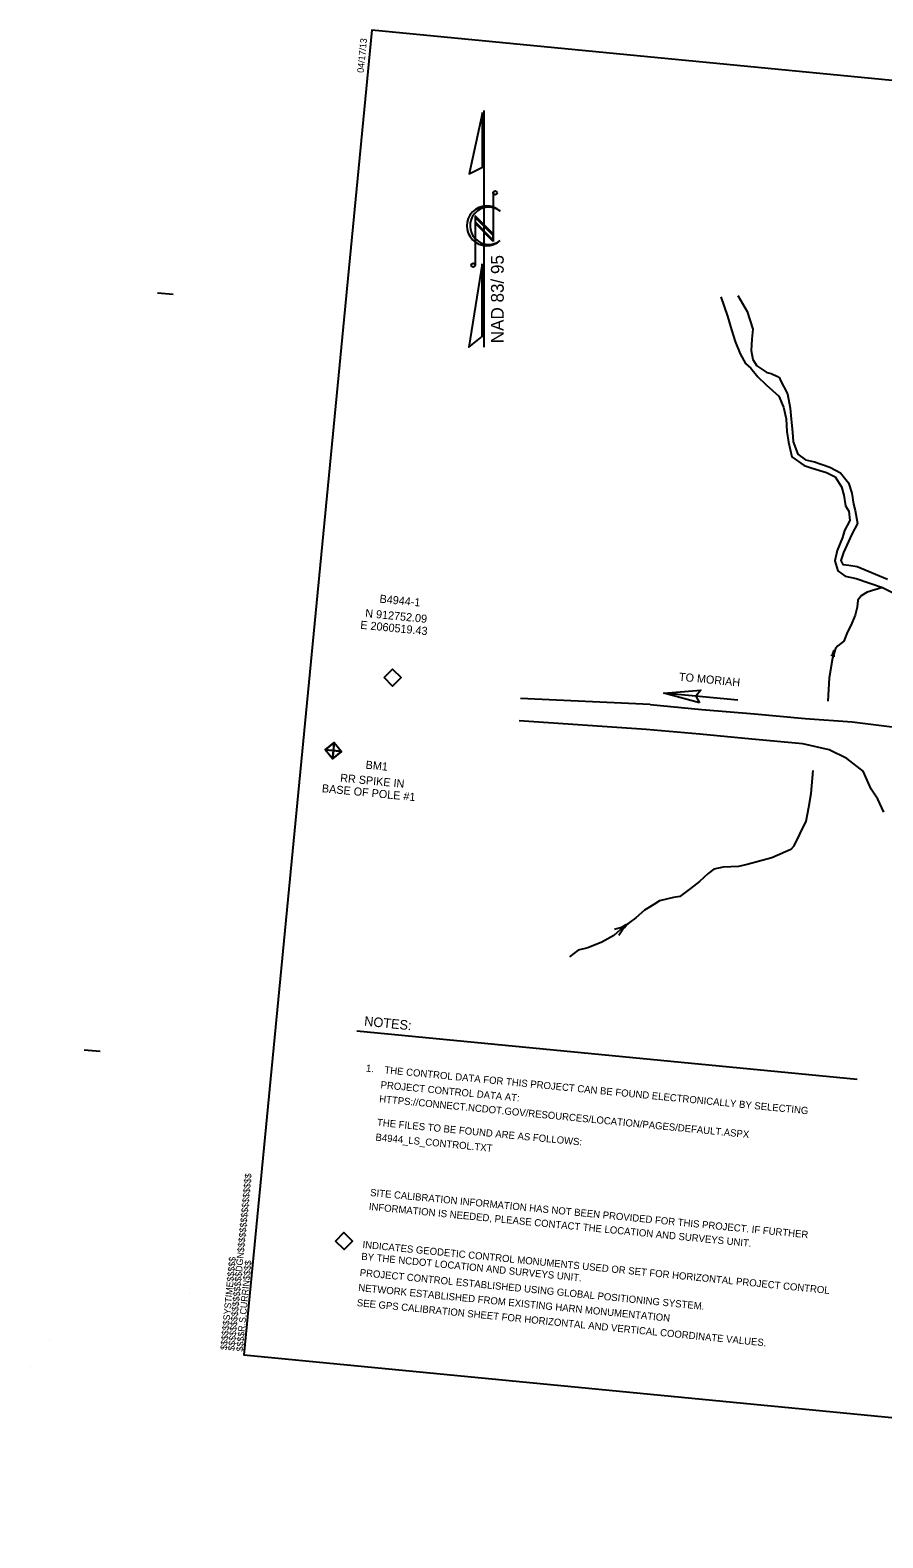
# Model space of a CAD drawing. Extents: x 2060504 to 2061945, y 912229 to 913160.
# Drawn here: x 2060504 to 2061030, y 912229 to 913160 of the extents above; entities that cross this region are included whole.
import ezdxf

# ---------------------------------------------------------------- set-up
doc = ezdxf.new("R2010")
doc.units = 0
for name, color, linetype in [('CTL Bench Mark CELL', 7, 'Continuous'), ('CTL Bench Mark Text', 7, 'Continuous'), ('CTL Sheet Border CELL', 7, 'Continuous'), ('CTL Sheet Notes CELL', 7, 'Continuous'), ('CTL Supplemental Horizontal and Vertical CELL', 7, 'Continuous'), ('Exist Hydro Jurisdictional Stream or Body of Water', 7, 'Continuous'), ('Exist Hydro Stream Flow Arrow CELL', 7, 'Continuous'), ('Exist Hydro Stream or Body of Water', 7, 'Continuous'), ('Exist Roads Soil', 7, 'Continuous'), ('Prop Terminator CELL', 7, 'Continuous'), ('Sheet Data Field CELL', 7, 'Continuous'), ('Sheet North Arrow CELL', 7, 'Continuous')]:
    doc.layers.add(name, color=color, linetype=linetype)

# ---------------------------------------------------------------- blocks, each defined once
blk = doc.blocks.new('EXIST HYDRO STREAM FLOW ARROW')
at = {"layer": 'Exist Hydro Stream Flow Arrow CELL'}
blk.add_line((0, 0), (0, 0), dxfattribs=at)
for points in [[(-0.1, 0.04575), (-0.07325, 0.03375), (-0.04475, 0.0245), (-0.0165, 0.01575), (0.01175, 0.0095), (0.041, 0.00475), (0.07075, 0.0015), (0.1, 0)], [(-0.1, -0.04575), (-0.07325, -0.03375), (-0.04475, -0.0245), (-0.0165, -0.01575), (0.01175, -0.0095), (0.041, -0.00475), (0.07075, -0.0015), (0.1, 0)]]:
    blk.add_lwpolyline(points, dxfattribs=at)

msp = doc.modelspace()

# ---------------------------------------------------------------- linework, layer by layer
at = {"layer": 'CTL Bench Mark CELL'}
msp.add_line((2060690.76, 912715.17), (2060690.76, 912715.17), dxfattribs=at)
msp.add_lwpolyline([(2060685.7, 912715.65), (2060691.26, 912720.22), (2060695.82, 912714.66), (2060690.27, 912710.1)], close=True, dxfattribs=at)
for points in [[(2060691.26, 912720.22), (2060690.27, 912710.1), (2060690.76, 912715.16), (2060695.82, 912714.66), (2060685.7, 912715.65)], [(2060690.76, 912715.16), (2060691.26, 912720.22), (2060685.7, 912715.65), (2060690.76, 912715.16)], [(2060690.76, 912715.16), (2060690.27, 912710.1), (2060695.82, 912714.66), (2060690.76, 912715.16)]]:
    msp.add_lwpolyline(points, dxfattribs=at)
at = {"layer": 'CTL Sheet Border CELL'}
for p, q in [((2060582.11, 912997.84), (2060591.84, 912996.9)), ((2060536.93, 912530.45), (2060546.66, 912529.51)), ((2060602.11, 912380.06), (2060602.11, 912380.06)), ((2060602.11, 912380.06), (2060602.11, 912380.06)), ((2060515.32, 912351.66), (2060515.32, 912351.66)), ((2060635.47, 912342.05), (2060635.47, 912342.05)), ((2060635.47, 912342.05), (2060635.47, 912342.05)), ((2060635.47, 912342.05), (2060635.47, 912342.05)), ((2060635.47, 912342.05), (2060635.47, 912342.05)), ((2060635.47, 912342.05), (2060635.47, 912342.05)), ((2060635.47, 912342.05), (2060635.47, 912342.05)), ((2060635.47, 912342.05), (2060635.47, 912342.05)), ((2060635.47, 912342.05), (2060635.47, 912342.05)), ((2060635.47, 912342.05), (2060635.47, 912342.05)), ((2060635.47, 912342.05), (2060635.47, 912342.05)), ((2060635.47, 912342.05), (2060635.47, 912342.05)), ((2060503.5, 912335.15), (2060503.5, 912335.15))]:
    msp.add_line(p, q, dxfattribs=at)
msp.add_lwpolyline([(2061883, 913047.03), (2060714.54, 913159.97), (2060635.47, 912342.05), (2061803.94, 912229.1)], close=True, dxfattribs=at)
for points in [[(2060631.32, 912377.23), (2060631.32, 912377.23)], [(2060631.32, 912377.23), (2060631.32, 912377.23)], [(2060664.69, 912339.23), (2060664.69, 912339.23)], [(2060664.69, 912339.23), (2060664.69, 912339.23)]]:
    msp.add_lwpolyline(points, dxfattribs=at)
at = {"layer": 'CTL Sheet Notes CELL'}
msp.add_line((2060705.3, 912542.22), (2061014.18, 912512.36), dxfattribs=at)
at = {"layer": 'CTL Supplemental Horizontal and Vertical CELL'}
for p, q in [((2060727.32, 912760.25), (2060727.32, 912760.25)), ((2060697.31, 912412.34), (2060697.31, 912412.34))]:
    msp.add_line(p, q, dxfattribs=at)
for points in [[(2060722.11, 912760.26), (2060727.35, 912765.51), (2060732.6, 912760.26), (2060727.36, 912755.01)], [(2060692.09, 912412.35), (2060697.34, 912417.59), (2060702.59, 912412.34), (2060697.35, 912407.1)]]:
    msp.add_lwpolyline(points, close=True, dxfattribs=at)
at = {"layer": 'Exist Hydro Jurisdictional Stream or Body of Water'}
for points in [[(2060929.98, 912995.34), (2060934.16, 912983.33), (2060936.63, 912974.98), (2060939.02, 912967.69), (2060942.1, 912960.23), (2060945.31, 912954.23), (2060948.55, 912951.35), (2060952.86, 912945.93), (2060958.18, 912940.97), (2060965.85, 912933.99), (2060968.7, 912927.22), (2060970.5, 912919.92), (2060970.92, 912912.26), (2060971.81, 912905.61), (2060973.92, 912896.46), (2060981.47, 912891.19), (2060986.43, 912889.46), (2060995.43, 912886.83), (2061000.78, 912884.21), (2061004.52, 912878.09), (2061006.09, 912872.96), (2061007.12, 912866.3), (2061009.14, 912862.9), (2061009.67, 912857.29), (2061006.56, 912851.08), (2061005.14, 912846.72), (2061001.9, 912838.78), (2061000.45, 912832.28), (2061002.25, 912826.14), (2061006.97, 912822.78), (2061013.64, 912821.5), (2061029.97, 912815.9), (2061040.31, 912810.63)], [(2060940.53, 912996.22), (2060946.26, 912986.22), (2060949.78, 912975.29), (2060949.15, 912969.19), (2060948.85, 912962.29), (2060949.93, 912956.68), (2060952.26, 912952.75), (2060958.51, 912948.61), (2060961.18, 912947.94), (2060965.13, 912946.17), (2060966.32, 912945.33), (2060966.91, 912943.59), (2060971.27, 912935.35), (2060972.99, 912926.62), (2060973.43, 912919.77), (2060974.35, 912911.81), (2060974.73, 912905.72), (2060977.66, 912898.19), (2060982.47, 912894.78), (2060987.9, 912893.36), (2060997.5, 912890.13), (2061004.09, 912886.61), (2061008.97, 912880.43), (2061010.92, 912874.07), (2061011.96, 912867.37), (2061013.14, 912863.3), (2061014.56, 912855.33), (2061010.99, 912848.88), (2061008.99, 912844.33), (2061005.74, 912837.45), (2061004.24, 912832.54), (2061005.45, 912830.03), (2061009.05, 912829.56), (2061014.35, 912828.84), (2061033.04, 912820.93)]]:
    msp.add_lwpolyline(points, dxfattribs=at)
at = {"layer": 'Exist Hydro Stream or Body of Water'}
for points in [[(2061029.97, 912815.9), (2061020.38, 912812.95), (2061016.81, 912810.63), (2061014.66, 912808.08), (2061014.37, 912803.65), (2061013.1, 912798.86), (2061010.89, 912793.76), (2061007.9, 912787.55), (2061006.04, 912782.74), (2061002.42, 912779.79), (2061000.81, 912778.16), (2060999.05, 912772.31), (2060997.07, 912760.16), (2060996.22, 912745.59)], [(2060973.25, 912654.18), (2060975.4, 912656.3), (2060978.82, 912663.48), (2060982.77, 912671.49), (2060984.48, 912680.26), (2060985.77, 912688.73), (2060987.17, 912702.89)], [(2060973.25, 912654.18), (2060961.52, 912649), (2060946.34, 912644.77), (2060940.96, 912643.7), (2060931.5, 912643.28), (2060925.67, 912642.01), (2060922.27, 912639.32), (2060916.97, 912634.43), (2060911.4, 912630.07), (2060904.68, 912625.12), (2060900.78, 912624.42), (2060892.16, 912622.37), (2060888.71, 912620.12), (2060882.89, 912616.64), (2060877.51, 912611.95), (2060869.79, 912606.07), (2060864.04, 912600.9), (2060856.53, 912596.9), (2060848.02, 912593.44), (2060841.95, 912591.92), (2060836.52, 912587.91)]]:
    msp.add_lwpolyline(points, dxfattribs=at)
at = {"layer": 'Exist Roads Soil'}
for points in [[(2060886.37, 912743.53), (2060806.37, 912747.43)], [(2060886.37, 912743.53), (2060918.27, 912740.51), (2060950.89, 912737.85), (2060982.11, 912734.98), (2061011.2, 912732.95), (2061042.39, 912729.02), (2061075.76, 912726.94), (2061092.95, 912725.5)], [(2060883.98, 912728.25), (2060805.57, 912733.45)], [(2061023.03, 912691.3), (2061017.95, 912702.36), (2061007.88, 912710.22), (2060996.93, 912715.54), (2060980.63, 912719.42), (2060949.3, 912722.16), (2060917.11, 912725.29), (2060883.98, 912728.25)], [(2061030.78, 912677.17), (2061026.96, 912685.13), (2061023.03, 912691.3)]]:
    msp.add_lwpolyline(points, dxfattribs=at)
at = {"layer": 'Prop Terminator CELL'}
msp.add_lwpolyline([(2060916.93, 912744.7), (2060894.91, 912750.72), (2060917.81, 912752.52), (2060914.56, 912748.82)], close=True, dxfattribs=at)
at = {"layer": 'Sheet Data Field CELL'}
msp.add_line((2060940.66, 912746.3), (2060894.91, 912750.72), dxfattribs=at)
at = {"layer": 'Sheet North Arrow CELL'}
for p, q in [((2060783.96, 912964.22), (2060783.96, 913110.47)), ((2060789.47, 913059.57), (2060789.47, 913029.56)), ((2060789.47, 913034.24), (2060778.29, 913045.42)), ((2060778.29, 913045.42), (2060778.29, 913014.91)), ((2060789.47, 913033.13), (2060778.29, 913044.32)), ((2060778.29, 913044.32), (2060778.29, 913041.57)), ((2060793.61, 913048.39), (2060793.77, 913048.28)), ((2060789.47, 913030.39), (2060778.29, 913041.57)), ((2060778.29, 913041.57), (2060789.47, 913030.39)), ((2060789.47, 913029.56), (2060778.29, 913040.74)), ((2060789.47, 913030.39), (2060789.47, 913033.13))]:
    msp.add_line(p, q, dxfattribs=at)
for points in [[(2060782.94, 913109.18), (2060774.6, 913071.2), (2060782.94, 913075.43)], [(2060782.76, 913015.74), (2060774.48, 912964.22), (2060782.76, 912970.74)]]:
    msp.add_lwpolyline(points, close=True, dxfattribs=at)
for centre in [(2060790.66, 913059.55), (2060777.1, 913014.86)]:
    msp.add_circle(centre, 1.19, dxfattribs=at)
for centre, radius, start, end in [((2060785.51, 913039.17), 12.29, 47.84002, 312.39406), ((2060786.7, 913039.17), 11.52, 53.09504, 308.62871)]:
    msp.add_arc(centre, radius, start, end, dxfattribs=at)

# ---------------------------------------------------------------- block references
at = {"layer": 'Exist Hydro Stream Flow Arrow CELL'}
for p, xscale, yscale, rotation in [((2060999.67, 912775.19), 20, 20.000000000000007, 77.64096278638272), ((2060869.79, 912606.07), 50, 50, 36.87182818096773)]:
    msp.add_blockref('EXIST HYDRO STREAM FLOW ARROW', p, dxfattribs=dict(at, xscale=xscale, yscale=yscale, rotation=rotation))

# ---------------------------------------------------------------- texts
at = {"layer": 'CTL Bench Mark Text'}
for s, p in [('N 912752.09', (2060710.27, 912797.65)), ('B4944-1', (2060719.12, 912806.53)), ('E 2060519.43', (2060707.24, 912790.41)), ('RR SPIKE IN ', (2060694.81, 912695.96)), ('BM1', (2060710.53, 912704)), ('BASE OF POLE #1', (2060683.51, 912689.52))]:
    msp.add_text(s, height=5, rotation=354.47872, dxfattribs=at).set_placement(p)
at = {"layer": 'CTL Sheet Border CELL'}
for s, height, p in [('04/17/13', 4.109, (2060709.51, 913133.48)), ('$$$$$$$$$$$$$$$$DGN$$$$$$$$$$$$$$$$', 4.1087, (2060629.7, 912344.46)), ('$$$$$$SYSTIME$$$$$', 4.1087, (2060624.99, 912344.92)), ('$$$$R.S.CURRIN$$$$', 4.1087, (2060634.82, 912343.98))]:
    msp.add_text(s, height=height, rotation=84.4787, dxfattribs=at).set_placement(p)
at = {"layer": 'CTL Sheet Notes CELL'}
for s, height, rotation, p in [('NOTES:', 5.884, 354.37345, (2060709.63, 912545.33)), ('1.    THE CONTROL DATA FOR THIS PROJECT CAN BE FOUND ELECTRONICALLY BY SELECTING', 4.4127, 354.4787, (2060710.74, 912517.01)), ('PROJECT CONTROL DATA AT:', 4.4127, 354.4787, (2060719.79, 912506.75)), ('HTTPS://CONNECT.NCDOT.GOV/RESOURCES/LOCATION/PAGES/DEFAULT.ASPX', 4.4127, 354.4787, (2060718.95, 912498.04)), ('THE FILES TO BE FOUND ARE AS FOLLOWS:', 4.4127, 354.4787, (2060717.55, 912483.53)), ('B4944_LS_CONTROL.TXT', 4.4127, 354.4787, (2060716.67, 912474.41)), ('SITE CALIBRATION INFORMATION HAS NOT BEEN PROVIDED FOR THIS PROJECT. IF FURTHER', 4.4127, 354.4787, (2060713.36, 912440.23)), ('INFORMATION IS NEEDED, PLEASE CONTACT THE LOCATION AND SURVEYS UNIT.', 4.4127, 354.4787, (2060712.53, 912431.58)), ('INDICATES GEODETIC CONTROL MONUMENTS USED OR SET FOR HORIZONTAL PROJECT CONTROL', 4.4127, 354.37345, (2060708.62, 912408.11)), ('BY THE NCDOT LOCATION AND SURVEYS UNIT.', 4.4127, 354.37345, (2060707.88, 912400.8)), ('PROJECT CONTROL ESTABLISHED USING GLOBAL POSITIONING SYSTEM.', 4.4127, 354.37345, (2060706.91, 912390.81)), ('NETWORK ESTABLISHED FROM EXISTING HARN MONUMENTATION', 4.4127, 354.37345, (2060706.01, 912381.52)), ('SEE GPS CALIBRATION SHEET FOR HORIZONTAL AND VERTICAL COORDINATE VALUES.', 4.4127, 354.37345, (2060705.11, 912372.21))]:
    msp.add_text(s, height=height, rotation=rotation, dxfattribs=at).set_placement(p)
at = {"layer": 'Sheet Data Field CELL'}
msp.add_text('TO MORIAH', height=5, rotation=354.4787, dxfattribs=at).set_placement((2060904.04, 912758.36))
at = {"layer": 'Sheet North Arrow CELL'}
msp.add_text('NAD 83/ 95', height=7.875, rotation=90, dxfattribs=at).set_placement((2060795.99, 912966.66))

doc.saveas('drawing.dxf')
